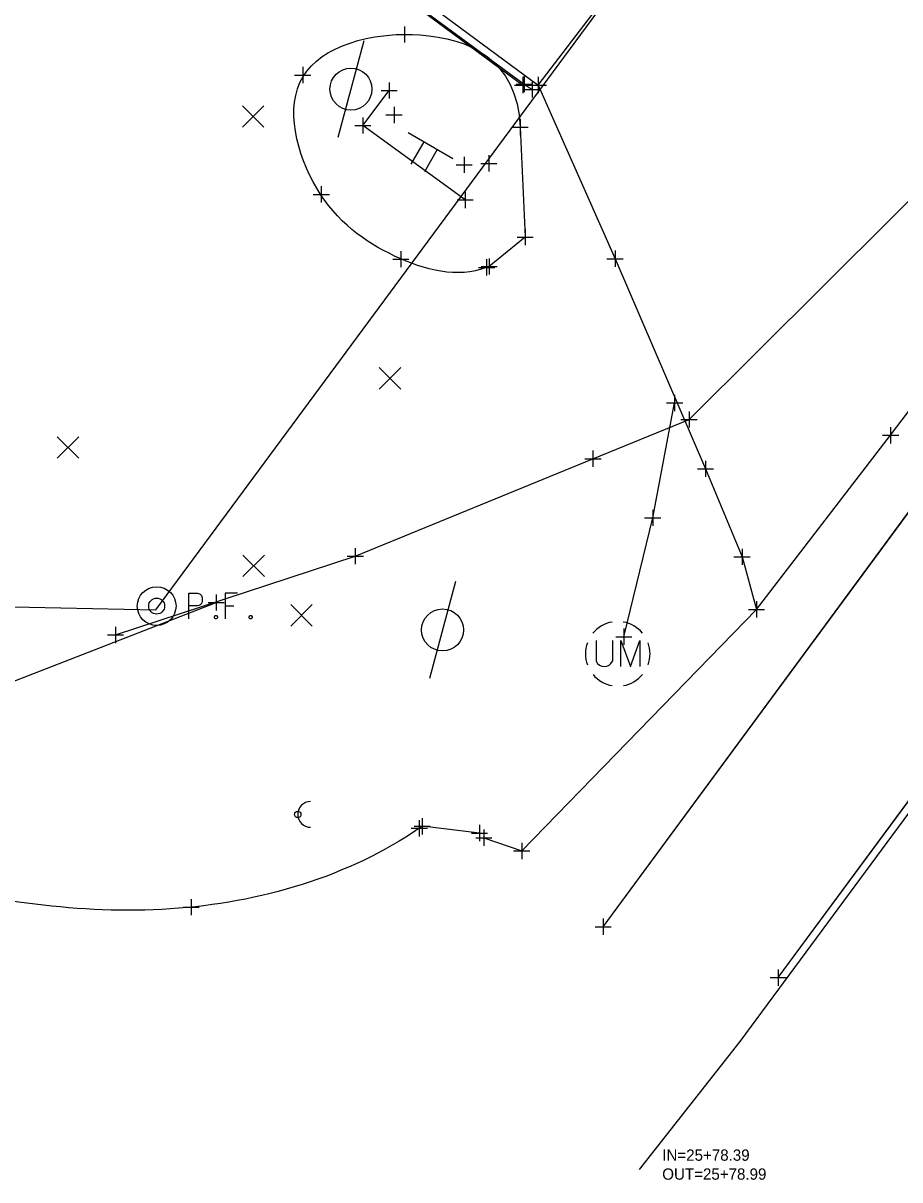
# Model space of a CAD drawing. Extents: x 1324089 to 1329959, y 459099 to 462017.
# Drawn here: x 1325440.5 to 1325494.9, y 460519 to 460590.6 of the extents above; entities that cross this region are included whole.
import ezdxf

# ---------------------------------------------------------------- set-up
doc = ezdxf.new("R2010")
doc.units = 0
for name, color, linetype in [('PM_X_CL_Double_Solid', 7, 'Continuous'), ('PM_X_Edge_Line', 7, 'Continuous'), ('PM_X_Surveyed_Line', 7, 'Continuous'), ('PV_X_Curb', 7, 'Continuous'), ('PV_X_Driveway', 7, 'Continuous'), ('PV_X_EOP', 7, 'Continuous'), ('PV_X_Shoulder_Aggregate', 7, 'Continuous'), ('RD_X_Concrete_Pad', 7, 'Continuous'), ('RW_X_CL', 7, 'Continuous'), ('RW_X_Fee_RW', 7, 'Continuous'), ('SN_X_Public', 7, 'Continuous'), ('SV_X_Break_Lines', 7, 'Continuous'), ('SV_X_Mon_Cells_Found', 7, 'Continuous'), ('SV_X_Random_Point', 7, 'Continuous'), ('SV_X_Shot_Marker', 7, 'Continuous'), ('UT_X_Misc_Cells', 7, 'Continuous'), ('UT_X_Telecom', 7, 'Continuous'), ('UT_X_Unknown_Cells', 7, 'Continuous'), ('VG_X_Flower_Bed', 7, 'Continuous')]:
    doc.layers.add(name, color=color, linetype=linetype)

msp = doc.modelspace()

# ---------------------------------------------------------------- linework, layer by layer
at = {"layer": 'PM_X_CL_Double_Solid'}
msp.add_line((1325487.31, 460531.49), (1325505.558, 460556.208), dxfattribs=at)
at = {"layer": 'PM_X_Edge_Line'}
msp.add_line((1325476.468, 460534.643), (1325497.311, 460562.916), dxfattribs=at)
at = {"layer": 'PM_X_Surveyed_Line'}
for points in [[(1325476.468, 460534.643), (1325497.311, 460562.916), (1325518.315, 460591.401), (1325539.274, 460619.828), (1325559.79, 460647.383), (1325579.721, 460674.061), (1325600.337, 460701.825), (1325621.689, 460730.614), (1325640.884, 460756.72), (1325660.886, 460784.382), (1325681.351, 460812.314), (1325701.967, 460840.182), (1325722.786, 460868.466), (1325742.91, 460895.719), (1325762.589, 460922.342), (1325781.839, 460948.459), (1325803.18, 460977.152), (1325823.469, 461004.355), (1325843.804, 461031.799), (1325864.413, 461059.129), (1325882.729, 461083.843)], [(1325487.31, 460531.49), (1325505.558, 460556.208), (1325527.376, 460585.354), (1325547.884, 460612.775), (1325568.496, 460640.752), (1325588.531, 460667.691), (1325609.182, 460695.622), (1325629.784, 460723.415), (1325649.854, 460750.691), (1325670.058, 460778.358), (1325689.988, 460805.971), (1325710.726, 460833.831), (1325731.558, 460861.892), (1325751.846, 460889.277), (1325771.48, 460915.921), (1325790.621, 460941.822), (1325811.714, 460970.267), (1325832.154, 460997.962), (1325852.519, 461025.379), (1325872.843, 461052.92), (1325891.559, 461078.179)]]:
    msp.add_lwpolyline(points, dxfattribs=at)
at = {"layer": 'PV_X_Curb'}
msp.add_lwpolyline([(1325456.513, 460598.622), (1325456.162, 460598.149), (1325463.89, 460592.494), (1325471.585, 460586.839), (1325472.079, 460586.507)], dxfattribs=at)
at = {"layer": 'PV_X_Driveway'}
msp.add_lwpolyline([(1325472.454, 460586.779), (1325477.205, 460576.02), (1325482.809, 460563.008), (1325485.074, 460557.555), (1325485.972, 460554.299)], dxfattribs=at)
at = {"layer": 'PV_X_EOP'}
for points in [[(1325469.073, 460540.154), (1325471.424, 460539.334), (1325485.972, 460554.299), (1325494.278, 460565.082), (1325514.219, 460591.32), (1325520.213, 460594.817), (1325539.099, 460619.967), (1325553.297, 460641.27), (1325558.068, 460648.609), (1325577.337, 460675.706), (1325586.918, 460689.041), (1325599.851, 460702.278), (1325620.929, 460731.198)], [(1325472.454, 460586.779), (1325480.715, 460597.605), (1325488.796, 460608.523), (1325500.806, 460624.673), (1325501.941, 460626.41)], [(1325432.112, 460616.351), (1325429.693, 460612.867), (1325435.952, 460608.056), (1325438.346, 460611.234), (1325449.827, 460602.698), (1325448.802, 460601.077), (1325452.314, 460598.444), (1325454.049, 460600.623), (1325456.401, 460598.67), (1325456.513, 460598.622), (1325464.163, 460592.903), (1325472.454, 460586.779)]]:
    msp.add_lwpolyline(points, dxfattribs=at)
at = {"layer": 'PV_X_Shoulder_Aggregate'}
for p, q in [((1325465.257, 460540.862), (1325465.08, 460540.741)), ((1325468.806, 460540.446), (1325465.257, 460540.862))]:
    msp.add_line(p, q, dxfattribs=at)
msp.add_lwpolyline([(1325477.756, 460552.608), (1325479.541, 460559.965), (1325480.897, 460567.085)], dxfattribs=at)
msp.add_open_spline([(1325465.08, 460540.741), (1325460.732, 460537.758), (1325449.725, 460534.464), (1325432.765, 460537.201), (1325418.152, 460541.918), (1325404.697, 460548.767), (1325391.277, 460554.853), (1325375.96, 460563.375), (1325364.225, 460563.404), (1325358.703, 460566.162)], degree=3, dxfattribs=at)
at = {"layer": 'RD_X_Concrete_Pad'}
msp.add_lwpolyline([(1325467.922, 460579.656), (1325461.588, 460584.271), (1325463.216, 460586.437)], dxfattribs=at)
at = {"layer": 'RW_X_CL'}
for p, q in [((1325484.957, 460527.536), (1326057.933, 461303.201)), ((1325478.732, 460519.599), (1325484.957, 460527.536))]:
    msp.add_line(p, q, dxfattribs=at)
at = {"layer": 'RW_X_Fee_RW'}
for p, q in [((1325448.762, 460554.274), (1326011.051, 461315.471)), ((1325207.409, 460559.259), (1325448.762, 460554.274))]:
    msp.add_line(p, q, dxfattribs=at)
at = {"layer": 'SN_X_Public'}
for p, q in [((1325464.392, 460583.829), (1325467.163, 460582.229)), ((1325465.362, 460583.269), (1325464.562, 460581.883)), ((1325466.193, 460582.789), (1325465.393, 460581.403)), ((1325465.777, 460583.029), (1325465.777, 460583.029))]:
    msp.add_line(p, q, dxfattribs=at)
at = {"layer": 'SV_X_Break_Lines'}
msp.add_lwpolyline([(1325456.077, 460598.033), (1325463.813, 460592.47), (1325471.485, 460586.779)], dxfattribs=at)
at = {"layer": 'SV_X_Mon_Cells_Found'}
for points in [[(1325450.809, 460553.703), (1325450.809, 460555.303), (1325451.338, 460555.303), (1325451.393, 460555.29), (1325451.471, 460555.265), (1325451.504, 460555.24), (1325451.537, 460555.215), (1325451.581, 460555.152), (1325451.614, 460555.089), (1325451.636, 460554.988), (1325451.636, 460554.837), (1325451.625, 460554.786), (1325451.603, 460554.711), (1325451.559, 460554.623), (1325451.515, 460554.585), (1325451.482, 460554.56), (1325451.426, 460554.534), (1325451.338, 460554.522), (1325450.809, 460554.522)], [(1325453.819, 460555.303), (1325453.058, 460555.303), (1325453.058, 460553.703)], [(1325452.452, 460553.917), (1325452.507, 460553.917), (1325452.54, 460553.892), (1325452.573, 460553.842), (1325452.573, 460553.779), (1325452.54, 460553.728), (1325452.507, 460553.703), (1325452.452, 460553.703), (1325452.419, 460553.728), (1325452.386, 460553.779), (1325452.386, 460553.842), (1325452.419, 460553.892), (1325452.452, 460553.917)], [(1325453.058, 460554.522), (1325453.598, 460554.522)], [(1325454.601, 460553.917), (1325454.656, 460553.917), (1325454.689, 460553.892), (1325454.722, 460553.842), (1325454.722, 460553.779), (1325454.689, 460553.728), (1325454.656, 460553.703), (1325454.601, 460553.703), (1325454.568, 460553.728), (1325454.535, 460553.779), (1325454.535, 460553.842), (1325454.568, 460553.892), (1325454.601, 460553.917)]]:
    msp.add_lwpolyline(points, dxfattribs=at)
for radius in [1.2, 0.495]:
    msp.add_circle((1325448.812, 460554.503), radius, dxfattribs=at)
at = {"layer": 'SV_X_Random_Point'}
for p, q in [((1325454.124, 460584.163), (1325455.457, 460585.498)), ((1325454.124, 460585.498), (1325455.457, 460584.163)), ((1325462.6, 460567.936), (1325463.934, 460569.271)), ((1325462.6, 460569.271), (1325463.934, 460567.936)), ((1325442.648, 460563.658), (1325443.981, 460564.993)), ((1325442.648, 460564.993), (1325443.981, 460563.658)), ((1325454.158, 460556.326), (1325455.492, 460557.661)), ((1325454.158, 460557.661), (1325455.492, 460556.326)), ((1325457.114, 460553.26), (1325458.447, 460554.595)), ((1325457.114, 460554.595), (1325458.447, 460553.26))]:
    msp.add_line(p, q, dxfattribs=at)
at = {"layer": 'SV_X_Shot_Marker'}
for p, q in [((1325464.154, 460590.402), (1325464.154, 460589.402)), ((1325463.654, 460589.902), (1325464.654, 460589.902)), ((1325464.154, 460589.902), (1325464.154, 460589.902)), ((1325457.86, 460587.895), (1325457.86, 460586.895)), ((1325457.36, 460587.395), (1325458.36, 460587.395)), ((1325457.86, 460587.395), (1325457.86, 460587.395)), ((1325463.216, 460586.937), (1325463.216, 460585.937)), ((1325471.085, 460586.839), (1325472.085, 460586.839)), ((1325471.485, 460587.279), (1325471.485, 460586.279)), ((1325471.585, 460587.339), (1325471.585, 460586.339)), ((1325471.585, 460586.839), (1325471.585, 460586.839)), ((1325472.079, 460587.007), (1325472.079, 460586.007)), ((1325472.454, 460587.279), (1325472.454, 460586.279)), ((1325472.454, 460587.279), (1325472.454, 460586.279)), ((1325472.454, 460587.279), (1325472.454, 460586.279)), ((1325462.716, 460586.437), (1325463.716, 460586.437)), ((1325463.216, 460586.437), (1325463.216, 460586.437)), ((1325470.985, 460586.779), (1325471.985, 460586.779)), ((1325471.485, 460586.779), (1325471.485, 460586.779)), ((1325471.579, 460586.507), (1325472.579, 460586.507)), ((1325471.954, 460586.779), (1325472.954, 460586.779)), ((1325471.954, 460586.779), (1325472.954, 460586.779)), ((1325471.954, 460586.779), (1325472.954, 460586.779)), ((1325472.079, 460586.507), (1325472.079, 460586.507)), ((1325472.454, 460586.779), (1325472.454, 460586.779)), ((1325472.454, 460586.779), (1325472.454, 460586.779)), ((1325472.454, 460586.779), (1325472.454, 460586.779)), ((1325463.515, 460585.424), (1325463.515, 460584.424)), ((1325461.588, 460584.771), (1325461.588, 460583.771)), ((1325463.015, 460584.924), (1325464.015, 460584.924)), ((1325463.515, 460584.924), (1325463.515, 460584.924)), ((1325471.332, 460584.669), (1325471.332, 460583.669)), ((1325461.088, 460584.271), (1325462.088, 460584.271)), ((1325461.588, 460584.271), (1325461.588, 460584.271)), ((1325470.832, 460584.169), (1325471.832, 460584.169)), ((1325471.332, 460584.169), (1325471.332, 460584.169)), ((1325467.356, 460581.833), (1325468.356, 460581.833)), ((1325467.856, 460582.333), (1325467.856, 460581.333)), ((1325467.856, 460581.833), (1325467.856, 460581.833)), ((1325468.893, 460581.924), (1325469.893, 460581.924)), ((1325469.393, 460582.424), (1325469.393, 460581.424)), ((1325469.393, 460581.924), (1325469.393, 460581.924)), ((1325459.011, 460580.505), (1325459.011, 460579.505)), ((1325458.511, 460580.005), (1325459.511, 460580.005)), ((1325459.011, 460580.005), (1325459.011, 460580.005)), ((1325467.422, 460579.656), (1325468.422, 460579.656)), ((1325467.922, 460580.156), (1325467.922, 460579.156)), ((1325467.922, 460579.656), (1325467.922, 460579.656)), ((1325471.64, 460577.856), (1325471.64, 460576.856)), ((1325471.64, 460577.856), (1325471.64, 460576.856)), ((1325471.14, 460577.356), (1325472.14, 460577.356)), ((1325471.14, 460577.356), (1325472.14, 460577.356)), ((1325471.64, 460577.356), (1325471.64, 460577.356)), ((1325471.64, 460577.356), (1325471.64, 460577.356)), ((1325463.943, 460576.49), (1325463.943, 460575.49)), ((1325477.205, 460576.52), (1325477.205, 460575.52)), ((1325463.443, 460575.99), (1325464.443, 460575.99)), ((1325463.943, 460575.99), (1325463.943, 460575.99)), ((1325468.752, 460575.481), (1325469.752, 460575.481)), ((1325468.907, 460575.54), (1325469.907, 460575.54)), ((1325469.252, 460575.981), (1325469.252, 460574.981)), ((1325469.252, 460575.481), (1325469.252, 460575.481)), ((1325469.407, 460576.04), (1325469.407, 460575.04)), ((1325469.407, 460575.54), (1325469.407, 460575.54)), ((1325476.705, 460576.02), (1325477.705, 460576.02)), ((1325477.205, 460576.02), (1325477.205, 460576.02)), ((1325480.897, 460567.585), (1325480.897, 460566.585)), ((1325480.397, 460567.085), (1325481.397, 460567.085)), ((1325480.897, 460567.085), (1325480.897, 460567.085)), ((1325481.29, 460566.057), (1325482.29, 460566.057)), ((1325481.79, 460566.557), (1325481.79, 460565.557)), ((1325481.79, 460566.057), (1325481.79, 460566.057)), ((1325494.278, 460565.582), (1325494.278, 460564.582)), ((1325493.778, 460565.082), (1325494.778, 460565.082)), ((1325494.278, 460565.082), (1325494.278, 460565.082)), ((1325475.838, 460564.13), (1325475.838, 460563.13)), ((1325475.338, 460563.63), (1325476.338, 460563.63)), ((1325475.838, 460563.63), (1325475.838, 460563.63)), ((1325482.809, 460563.508), (1325482.809, 460562.508)), ((1325482.309, 460563.008), (1325483.309, 460563.008)), ((1325482.809, 460563.008), (1325482.809, 460563.008)), ((1325479.541, 460560.465), (1325479.541, 460559.465)), ((1325479.041, 460559.965), (1325480.041, 460559.965)), ((1325479.541, 460559.965), (1325479.541, 460559.965)), ((1325460.618, 460557.593), (1325461.618, 460557.593)), ((1325461.118, 460558.093), (1325461.118, 460557.093)), ((1325461.118, 460557.593), (1325461.118, 460557.593)), ((1325484.574, 460557.555), (1325485.574, 460557.555)), ((1325485.074, 460558.055), (1325485.074, 460557.055)), ((1325485.074, 460557.555), (1325485.074, 460557.555)), ((1325451.995, 460554.72), (1325452.995, 460554.72)), ((1325452.495, 460555.22), (1325452.495, 460554.22)), ((1325452.495, 460554.72), (1325452.495, 460554.72)), ((1325485.972, 460554.799), (1325485.972, 460553.799)), ((1325485.472, 460554.299), (1325486.472, 460554.299)), ((1325485.972, 460554.299), (1325485.972, 460554.299)), ((1325446.264, 460553.213), (1325446.264, 460552.213)), ((1325445.764, 460552.713), (1325446.764, 460552.713)), ((1325446.264, 460552.713), (1325446.264, 460552.713)), ((1325477.256, 460552.608), (1325478.256, 460552.608)), ((1325477.756, 460553.108), (1325477.756, 460552.108)), ((1325477.756, 460552.608), (1325477.756, 460552.608)), ((1325465.08, 460541.241), (1325465.08, 460540.241)), ((1325465.257, 460541.362), (1325465.257, 460540.362)), ((1325468.806, 460540.946), (1325468.806, 460539.946)), ((1325464.58, 460540.741), (1325465.58, 460540.741)), ((1325464.757, 460540.862), (1325465.757, 460540.862)), ((1325465.08, 460540.741), (1325465.08, 460540.741)), ((1325465.257, 460540.862), (1325465.257, 460540.862)), ((1325468.306, 460540.446), (1325469.306, 460540.446)), ((1325468.806, 460540.446), (1325468.806, 460540.446)), ((1325469.073, 460540.654), (1325469.073, 460539.654)), ((1325468.573, 460540.154), (1325469.573, 460540.154)), ((1325469.073, 460540.154), (1325469.073, 460540.154)), ((1325471.424, 460539.834), (1325471.424, 460538.834)), ((1325470.924, 460539.334), (1325471.924, 460539.334)), ((1325471.424, 460539.334), (1325471.424, 460539.334)), ((1325450.953, 460536.355), (1325450.953, 460535.355)), ((1325450.453, 460535.855), (1325451.453, 460535.855)), ((1325450.953, 460535.855), (1325450.953, 460535.855)), ((1325475.968, 460534.643), (1325476.968, 460534.643)), ((1325476.468, 460535.143), (1325476.468, 460534.143)), ((1325476.468, 460534.643), (1325476.468, 460534.643)), ((1325487.31, 460531.99), (1325487.31, 460530.99)), ((1325486.81, 460531.49), (1325487.81, 460531.49)), ((1325487.31, 460531.49), (1325487.31, 460531.49))]:
    msp.add_line(p, q, dxfattribs=at)
at = {"layer": 'UT_X_Misc_Cells'}
msp.add_circle((1325457.55, 460541.599), 0.2, dxfattribs=at)
msp.add_arc((1325458.35, 460541.599), 0.8, 90, 270, dxfattribs=at)
at = {"layer": 'UT_X_Telecom'}
for points in [[(1325446.264, 460552.713), (1325461.118, 460557.593), (1325475.838, 460563.63), (1325481.79, 460566.057), (1325498.598, 460582.79), (1325515.22, 460604.335)], [(1325283.127, 460549.925), (1325297.628, 460549.066), (1325329.69, 460550.539), (1325353.856, 460550.993), (1325382.42, 460549.438), (1325404.707, 460544.407), (1325418.364, 460542.533), (1325426.905, 460542.187), (1325439.002, 460549.488), (1325452.495, 460554.72)]]:
    msp.add_lwpolyline(points, dxfattribs=at)
at = {"layer": 'UT_X_Unknown_Cells'}
for p, q in [((1325461.651, 460589.523), (1325460.044, 460583.523)), ((1325467.324, 460556.024), (1325465.717, 460550.024)), ((1325476.032, 460552.361), (1325476.032, 460551.081)), ((1325477.04, 460552.361), (1325477.04, 460551.081)), ((1325477.373, 460551.546), (1325477.373, 460551.546))]:
    msp.add_line(p, q, dxfattribs=at)
msp.add_lwpolyline([(1325477.562, 460550.761), (1325477.562, 460552.361), (1325478.155, 460550.761), (1325478.747, 460552.361), (1325478.747, 460550.761)], dxfattribs=at)
for centre in [(1325460.848, 460586.523), (1325466.52, 460553.024)]:
    msp.add_circle(centre, 1.3, dxfattribs=at)
for centre, radius, start, end in [((1325477.373, 460551.546), 2, 100.0806, 140.07213), ((1325477.373, 460551.546), 2, 40.05767, 80.10608), ((1325477.373, 460551.546), 2, 160.01689, 200.03919), ((1325477.373, 460551.546), 2, 340.01689, 20.03919), ((1325476.536, 460551.319), 0.557, 205.19243, 334.80757), ((1325477.373, 460551.546), 2, 220.05767, 260.04731), ((1325477.373, 460551.546), 2, 280.01144, 320.02638)]:
    msp.add_arc(centre, radius, start, end, dxfattribs=at)
at = {"layer": 'VG_X_Flower_Bed'}
for p, q in [((1325471.332, 460584.169), (1325471.64, 460577.356)), ((1325471.64, 460577.356), (1325469.407, 460575.54)), ((1325469.407, 460575.54), (1325469.252, 460575.481))]:
    msp.add_line(p, q, dxfattribs=at)
msp.add_open_spline([(1325469.252, 460575.481), (1325467.427, 460574.781), (1325463.411, 460575.828), (1325458.245, 460579.542), (1325455.969, 460588.328), (1325465.142, 460590.954), (1325471.141, 460588.404), (1325471.332, 460584.169)], degree=3, dxfattribs=at)

# ---------------------------------------------------------------- texts
at = {"layer": 'RW_X_CL'}
for s, p in [('IN=25+78.39', (1325480.131, 460520.146)), ('OUT=25+78.99', (1325480.131, 460518.972))]:
    msp.add_text(s, height=0.7, dxfattribs=at).set_placement(p)

doc.saveas('drawing.dxf')
